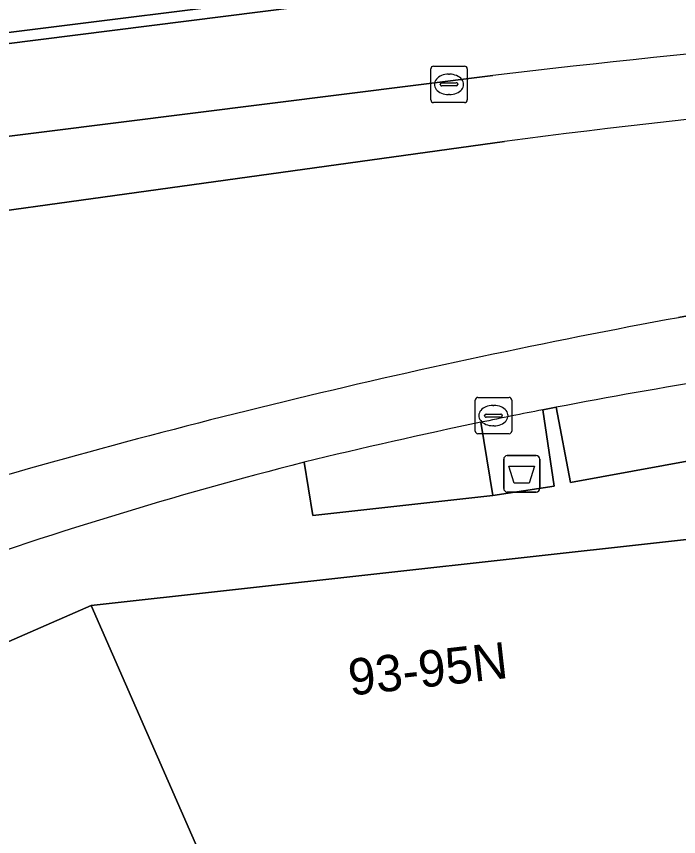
# Model space of a CAD drawing. Extents: x 160663 to 161506, y 382245 to 383291.
# Drawn here: x 161024.4 to 161042.57, y 382914.09 to 382936.61 of the extents above; entities that cross this region are included whole.
import ezdxf

# ---------------------------------------------------------------- set-up
doc = ezdxf.new("R2010")
doc.units = 0
for name, color, linetype in [('IMGEO_Afval_apart_plaats', 7, 'Continuous'), ('IMGEO_Groenvoorziening', 7, 'Continuous'), ('IMGEO_Kolk', 7, 'Continuous'), ('IMGEO_Pand', 7, 'Continuous'), ('IMGEO_Pand_nummerreeks', 7, 'Continuous'), ('IMGEO_Parkeervlak_open', 7, 'Continuous'), ('IMGEO_Rijbaan_lokaal_gesloten', 7, 'Continuous'), ('IMGEO_Voetpad_gesloten', 7, 'Continuous'), ('IMGEO_Voetpad_open', 7, 'Continuous')]:
    doc.layers.add(name, color=color, linetype=linetype)

msp = doc.modelspace()

# ---------------------------------------------------------------- linework, layer by layer
at = {"layer": 'IMGEO_Afval_apart_plaats'}
for p, q in [((161037.77, 382923.649), (161037.77, 382924.449)), ((161037.77, 382924.449), (161037.77, 382923.649)), ((161037.87, 382924.549), (161038.66, 382924.549)), ((161038.66, 382924.549), (161037.87, 382924.549)), ((161038.76, 382924.449), (161038.76, 382923.649)), ((161038.76, 382923.649), (161038.76, 382924.449)), ((161038.66, 382923.549), (161037.87, 382923.549)), ((161037.87, 382923.549), (161038.66, 382923.549))]:
    msp.add_line(p, q, dxfattribs=at)
msp.add_lwpolyline([(161037.913, 382924.263), (161038.617, 382924.263), (161038.468, 382923.793), (161038.062, 382923.793), (161037.913, 382924.263)], dxfattribs=at)
for centre, start, end in [((161037.87, 382924.449), 90, 180), ((161037.87, 382924.449), 90, 180), ((161038.66, 382924.449), 0, 90), ((161038.66, 382924.449), 360, 90), ((161037.87, 382923.649), 180, 270), ((161037.87, 382923.649), 180, 270), ((161038.66, 382923.649), 270, 0), ((161038.66, 382923.649), 270, 0)]:
    msp.add_arc(centre, 0.1, start, end, dxfattribs=at)
at = {"layer": 'IMGEO_Groenvoorziening'}
msp.add_lwpolyline([(161032.294, 382924.367), (161032.535, 382922.904), (161037.474, 382923.453), (161037.147, 382925.465)], dxfattribs=at)
msp.add_arc((161066.518, 382784.376), 144.113, 101.75949, 103.73778, dxfattribs=at)
at = {"layer": 'IMGEO_Kolk'}
for p, q in [((161035.845, 382935.243), (161036.697, 382935.243)), ((161035.77, 382934.317), (161035.77, 382935.169)), ((161036.258, 382935.023), (161036.283, 382935.023)), ((161036.771, 382935.169), (161036.771, 382934.317)), ((161036.029, 382934.737), (161036.029, 382934.749)), ((161036.467, 382934.7), (161036.069, 382934.7)), ((161036.072, 382934.786), (161036.47, 382934.786)), ((161036.513, 382934.749), (161036.513, 382934.737)), ((161036.281, 382934.463), (161036.256, 382934.463)), ((161036.697, 382934.243), (161035.845, 382934.243)), ((161036.989, 382925.222), (161036.989, 382926.074)), ((161037.064, 382926.148), (161037.916, 382926.148)), ((161037.99, 382926.074), (161037.99, 382925.222)), ((161037.477, 382925.928), (161037.502, 382925.928)), ((161037.248, 382925.642), (161037.248, 382925.654)), ((161037.686, 382925.605), (161037.288, 382925.605)), ((161037.291, 382925.691), (161037.689, 382925.691)), ((161037.732, 382925.654), (161037.732, 382925.642)), ((161037.5, 382925.368), (161037.475, 382925.368)), ((161037.916, 382925.148), (161037.064, 382925.148))]:
    msp.add_line(p, q, dxfattribs=at)
for points in [[(161035.845, 382935.243), (161036.697, 382935.243)], [(161035.77, 382934.317), (161035.77, 382935.169)], [(161036.771, 382935.169), (161036.771, 382934.317)], [(161036.697, 382934.243), (161035.845, 382934.243)], [(161036.989, 382925.222), (161036.989, 382926.074)], [(161037.064, 382926.148), (161037.916, 382926.148)], [(161037.99, 382926.074), (161037.99, 382925.222)], [(161037.916, 382925.148), (161037.064, 382925.148)]]:
    msp.add_lwpolyline(points, dxfattribs=at)
for centre, radius, start, end in [((161035.847, 382935.167), 0.0765, 91.552, 178.448), ((161035.847, 382935.167), 0.0765, 91.552, 178.448), ((161036.695, 382935.167), 0.0765, 1.552, 88.448), ((161036.695, 382935.167), 0.0765, 1.552, 88.448), ((161036.069, 382934.746), 0.0403, 85.8775, 175.7526), ((161036.066, 382934.736), 0.0366, 178.938, 274.7102), ((161036.47, 382934.743), 0.043, 264.8664, 352.4533), ((161036.474, 382934.748), 0.0386, 1.7309, 96.639), ((161035.847, 382934.319), 0.0765, 181.552, 268.448), ((161035.847, 382934.319), 0.0765, 181.552, 268.448), ((161036.695, 382934.319), 0.0765, 271.552, 358.448), ((161036.695, 382934.319), 0.0765, 271.552, 358.448), ((161037.066, 382926.072), 0.0765, 91.552, 178.448), ((161037.066, 382926.072), 0.0765, 91.552, 178.448), ((161037.914, 382926.072), 0.0765, 1.552, 88.448), ((161037.914, 382926.072), 0.0765, 1.552, 88.448), ((161037.288, 382925.651), 0.0403, 85.8775, 175.7526), ((161037.285, 382925.641), 0.0366, 178.938, 274.7102), ((161037.689, 382925.648), 0.043, 264.8664, 352.4533), ((161037.693, 382925.653), 0.0386, 1.7309, 96.639), ((161037.066, 382925.224), 0.0765, 181.552, 268.448), ((161037.066, 382925.224), 0.0765, 181.552, 268.448), ((161037.914, 382925.224), 0.0765, 271.552, 358.448), ((161037.914, 382925.224), 0.0765, 271.552, 358.448)]:
    msp.add_arc(centre, radius, start, end, dxfattribs=at)
for centre, major_axis, ratio, start_param, end_param in [((161036.257, 382934.743), (-0.387, 0.002), 0.722429, 4.712389, 7.853982), ((161036.282, 382934.743), (-0.39, 0.002), 0.717154, 1.570796, 4.712389), ((161037.476, 382925.648), (-0.387, 0.002), 0.722429, 4.712389, 7.853982), ((161037.501, 382925.648), (-0.39, 0.002), 0.717154, 1.570796, 4.712389)]:
    msp.add_ellipse(centre, major_axis=major_axis, ratio=ratio, start_param=start_param, end_param=end_param, dxfattribs=at)
at = {"layer": 'IMGEO_Pand'}
msp.add_lwpolyline([(161051.047, 382948.629), (161030.591, 382945.988), (161029.691, 382947.061), (161035.646, 382953.903), (161037.824, 382952.128), (161044.516, 382960.343), (161041.689, 382964.766), (161038.598, 382967.297), (161038.784, 382967.513), (161038.171, 382968.031), (161030.23, 382958.317), (161027.298, 382954.73), (161017.805, 382943.117), (161016.711, 382941.779), (161019.776, 382935.622), (161036.201, 382937.674), (161048.363, 382939.194)], dxfattribs=at)
for points in [[(161046.345, 382922.64), (161046.091, 382922.612), (161026.456, 382920.431), (161033.8, 382903.661), (161037.932, 382905.534), (161040.011, 382900.714), (161041.864, 382901.513), (161040.595, 382904.367), (161044.474, 382906.103), (161046.544, 382901.321), (161050.966, 382903.262), (161057.902, 382904.07), (161051.502, 382912.053), (161051.861, 382912.341), (161047.527, 382917.746)], [(161024.827, 382901.808), (161027.01, 382896.764), (161035.229, 382900.358), (161033.8, 382903.661), (161026.456, 382920.431), (161022.658, 382918.777), (161022.735, 382918.593), (161020.035, 382917.387), (161020.603, 382916.161), (161017.496, 382913.799), (161018.294, 382911.972), (161018.193, 382911.923), (161022.524, 382902.347), (161023.07, 382901.081)]]:
    msp.add_lwpolyline(points, close=True, dxfattribs=at)
at = {"layer": 'IMGEO_Parkeervlak_open'}
msp.add_lwpolyline([(161039.209, 382925.877), (161039.6, 382923.81), (161057.369, 382927.06), (161057.022, 382929.08)], dxfattribs=at)
msp.add_arc((161065.921, 382787.01), 141.412, 99.07701, 100.88847, dxfattribs=at)
at = {"layer": 'IMGEO_Rijbaan_lokaal_gesloten'}
for points in [[(161037.47, 382934.988), (161025.093, 382933.433), (161020.977, 382932.92), (161013.66, 382932.007), (161011.513, 382931.727)], [(161011.778, 382929.564), (161037.79, 382933.174)], [(161037.79, 382933.174), (161011.778, 382929.564)], [(161056.554, 382930.899), (161042.569, 382928.337)], [(161042.569, 382928.337), (161056.554, 382930.899)], [(161038.841, 382925.806), (161039.209, 382925.877)]]:
    msp.add_lwpolyline(points, dxfattribs=at)
for centre, radius, start, end in [((161077.257, 382597.76), 339.566, 93.73679, 96.72873), ((161065.688, 382722.808), 212.208, 92.63145, 97.55421), ((161065.688, 382722.808), 212.208, 92.63145, 97.55421), ((161077.931, 382735.933), 195.626, 100.4143, 106.89826), ((161077.931, 382735.933), 195.626, 100.4143, 106.89826), ((161065.921, 382787.01), 141.412, 99.07701, 100.88847), ((161065.807, 382787.466), 140.943, 101.03023, 101.73269), ((161066.518, 382784.376), 144.113, 101.75949, 103.73778), ((161060.907, 382812.45), 115.517, 104.34124, 109.78901)]:
    msp.add_arc(centre, radius, start, end, dxfattribs=at)
at = {"layer": 'IMGEO_Voetpad_gesloten'}
msp.add_lwpolyline([(161037.147, 382925.465), (161037.474, 382923.453), (161039.159, 382923.709), (161038.841, 382925.806)], dxfattribs=at)
msp.add_arc((161065.807, 382787.466), 140.943, 101.03023, 101.73269, dxfattribs=at)
at = {"layer": 'IMGEO_Voetpad_open'}
for points in [[(161082.437, 382947.335), (161075.318, 382944.985), (161073.385, 382944.464), (161066.681, 382942.633), (161066.415, 382942.56), (161060.576, 382941.33), (161060.264, 382941.264), (161051.535, 382939.337), (161036.237, 382937.396), (161019.914, 382935.326), (161020.977, 382932.92), (161025.093, 382933.433), (161037.47, 382934.988)], [(161063.258, 382927.939), (161062.834, 382930.198), (161057.022, 382929.08), (161057.369, 382927.06), (161039.6, 382923.81), (161039.209, 382925.877), (161038.841, 382925.806), (161039.159, 382923.709), (161037.474, 382923.453), (161032.535, 382922.904), (161032.294, 382924.367)], [(161008.532, 382912.58), (161014.477, 382915.191), (161015.441, 382915.623), (161018.01, 382916.731), (161018.411, 382916.899), (161022.658, 382918.777), (161026.456, 382920.431), (161046.091, 382922.612)]]:
    msp.add_lwpolyline(points, dxfattribs=at)
msp.add_lwpolyline([(161019.776, 382935.622), (161019.914, 382935.326), (161036.237, 382937.396), (161051.535, 382939.337), (161060.264, 382941.264), (161059.642, 382941.393), (161052.359, 382939.817), (161048.363, 382939.194), (161036.201, 382937.674)], close=True, dxfattribs=at)
for centre, radius, start, end in [((161077.257, 382597.76), 339.566, 93.73679, 96.72873), ((161060.907, 382812.45), 115.517, 104.34124, 109.78901)]:
    msp.add_arc(centre, radius, start, end, dxfattribs=at)

# ---------------------------------------------------------------- texts
at = {"layer": 'IMGEO_Pand_nummerreeks'}
msp.add_text('93-95N', height=1, rotation=6.4117, dxfattribs=at).set_placement((161033.565, 382917.955))

doc.saveas('drawing.dxf')
